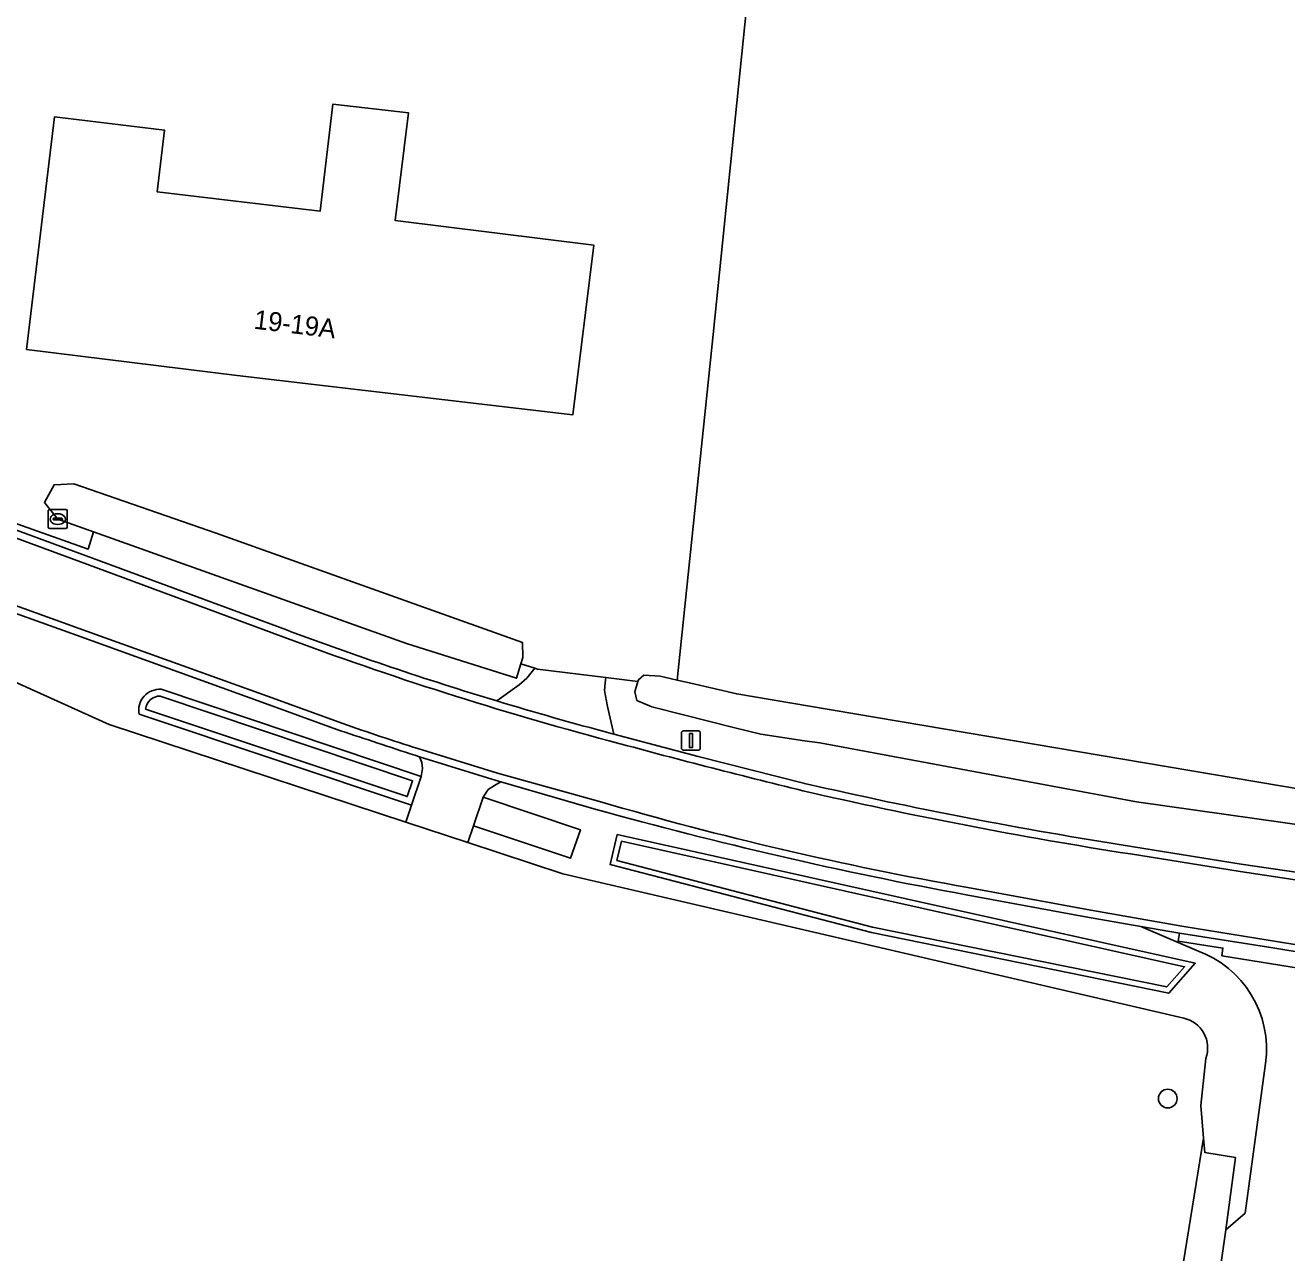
# Model space of a CAD drawing. Extents: x 162510 to 163918, y 388494 to 389774.
# Drawn here: x 162616.6 to 162682.9, y 389035.7 to 389100.2 of the extents above; entities that cross this region are included whole.
import ezdxf

# ---------------------------------------------------------------- set-up
doc = ezdxf.new("R2010")
doc.units = 0
for name, color, linetype in [('IMGEO_Berm_groen', 7, 'Continuous'), ('IMGEO_Boom', 7, 'Continuous'), ('IMGEO_Bouwland', 7, 'Continuous'), ('IMGEO_Erf', 7, 'Continuous'), ('IMGEO_Groenvoorziening', 7, 'Continuous'), ('IMGEO_Lichtmast', 7, 'Continuous'), ('IMGEO_Oever', 7, 'Continuous'), ('IMGEO_Pand', 7, 'Continuous'), ('IMGEO_Pand_nummerreeks', 7, 'Continuous'), ('IMGEO_Rijbaan_lokaal_gesloten', 7, 'Continuous'), ('IMGEO_Rijbaan_lokaal_halfverhard', 7, 'Continuous'), ('IMGEO_Rijbaan_lokaal_onverhard', 7, 'Continuous'), ('IMGEO_Rioolput', 7, 'Continuous'), ('IMGEO_Voetpad_open', 7, 'Continuous'), ('IMGEO_Waterloop', 7, 'Continuous')]:
    doc.layers.add(name, color=color, linetype=linetype)

msp = doc.modelspace()

# ---------------------------------------------------------------- linework, layer by layer
at = {"layer": 'IMGEO_Berm_groen'}
for points in [[(162599.769, 389075.181), (162599.005, 389075.013), (162598.439, 389074.769), (162598.136, 389073.919), (162597.772, 389072.896), (162605.424, 389070.178), (162605.91, 389071.318), (162613.301, 389068.852), (162612.506, 389067.31), (162621.016, 389063.464), (162636.603, 389058.338), (162636.901, 389059.229), (162622.591, 389064.006)], [(162633.167, 389063.141), (162629.224, 389064.578), (162619.309, 389068.164), (162606.622, 389072.695), (162599.769, 389075.181)], [(162623.752, 389065.315), (162637.408, 389060.743), (162637.478, 389061.162), (162637.435, 389061.466), (162637.328, 389061.772), (162637.079, 389061.849)]]:
    msp.add_lwpolyline(points, dxfattribs=at)
for centre, radius, start, end in [((162623.672, 389064.216), 1.102, 85.85497, 191.00304), ((163018.716, 390223.963), 1223.174, 251.626885, 251.819865)]:
    msp.add_arc(centre, radius, start, end, dxfattribs=at)
at = {"layer": 'IMGEO_Boom'}
msp.add_circle((162676.627, 389043.825), 0.489, dxfattribs=at)
at = {"layer": 'IMGEO_Bouwland'}
msp.add_lwpolyline([(162655.166, 389107.621), (162652.745, 389083.952), (162650.857, 389065.794), (162651.566, 389065.632), (162653.989, 389065.078), (162657.8, 389064.433), (162686.069, 389059.649), (162688.964, 389059.201), (162702.649, 389057.082), (162731.841, 389053.7), (162748.803, 389052.862), (162762.9, 389052.38), (162768.724, 389052.581), (162789.49, 389053.299), (162788.462, 389081.4), (162784.276, 389122.828)], dxfattribs=at)
at = {"layer": 'IMGEO_Erf'}
for points in [[(162610.637, 389075.969), (162619.919, 389072.683), (162620.188, 389073.585), (162618.326, 389074.249), (162617.612, 389075.122), (162618.128, 389076.056), (162619.16, 389076.114), (162626.637, 389073.516), (162642.734, 389067.769), (162642.75, 389066.991), (162642.646, 389066.648), (162643.381, 389066.421), (162643.518, 389066.379), (162647.102, 389065.938), (162648.643, 389065.749), (162648.795, 389065.73), (162648.82, 389065.815), (162649.111, 389066.053), (162649.957, 389066), (162650.857, 389065.794), (162652.745, 389083.952), (162655.166, 389107.621)], [(162677.463, 389048.046), (162644.844, 389055.627), (162639.858, 389057.267), (162636.603, 389058.338), (162621.016, 389063.464), (162612.506, 389067.31), (162605.424, 389070.178), (162597.772, 389072.896), (162592.401, 389074.784), (162572.538, 389080.978)], [(162663.551, 389030.577), (162675.729, 389028.773), (162674.379, 389019.647), (162674.908, 389019.57), (162678.508, 389041.745), (162678.361, 389043.464), (162678.629, 389045.931)]]:
    msp.add_lwpolyline(points, dxfattribs=at)
msp.add_lwpolyline([(162618.144, 389095.37), (162623.932, 389094.677), (162623.545, 389091.44), (162632.094, 389090.417), (162632.766, 389096.037), (162636.741, 389095.589), (162636.045, 389089.931), (162646.476, 389088.646), (162645.378, 389079.737), (162627.737, 389081.795), (162616.682, 389083.157)], close=True, dxfattribs=at)
msp.add_arc((162677.114, 389046.475), 1.609, 340.25405, 77.48187, dxfattribs=at)
at = {"layer": 'IMGEO_Groenvoorziening'}
for points in [[(162620.188, 389073.585), (162619.919, 389072.683), (162610.637, 389075.969), (162592.606, 389084.643), (162583.595, 389089.671), (162583.138, 389090.012), (162582.949, 389089.105), (162583.143, 389087.072), (162583.689, 389085.599), (162584.363, 389085.356), (162588.931, 389083.662), (162597.729, 389080.442), (162608.065, 389076.654), (162620.144, 389072.2), (162630.325, 389068.434)], [(162641.376, 389064.706), (162642.557, 389065.555), (162642.952, 389065.907), (162643.381, 389066.421), (162642.646, 389066.648), (162642.417, 389065.896), (162636.638, 389067.722), (162620.188, 389073.585)], [(162685.89, 389057.87), (162674.992, 389059.401), (162658.351, 389062.5), (162657.545, 389062.618), (162655.254, 389062.955), (162653.814, 389063.319), (162651.193, 389063.981), (162649.522, 389064.403), (162648.74, 389064.73), (162648.635, 389065.18), (162648.795, 389065.73), (162648.643, 389065.749), (162647.102, 389065.938), (162647.067, 389065.657), (162647.038, 389065.248), (162647.194, 389064.421), (162647.521, 389062.964), (162651.961, 389061.787), (162657.553, 389060.375)], [(162641.596, 389060.449), (162641.251, 389060.258), (162640.933, 389060.049), (162640.657, 389059.656), (162645.77, 389057.944), (162645.246, 389056.444), (162640.151, 389058.145), (162639.858, 389057.267), (162644.844, 389055.627), (162677.463, 389048.046)], [(162646.599, 389059.011), (162641.596, 389060.449)], [(162674.728, 389057.063), (162680.49, 389056.14), (162693.54, 389054.23), (162703.586, 389052.824), (162714.112, 389051.432), (162724.747, 389050.133), (162731.224, 389049.502)], [(162678.161, 389051.594), (162675.204, 389052.865), (162672.306, 389053.366), (162666.038, 389054.524)], [(162678.629, 389045.931), (162678.361, 389043.464), (162678.508, 389041.745), (162678.572, 389040.995), (162680.18, 389040.722), (162679.686, 389036.939), (162680.695, 389037.813), (162681.767, 389045.668)], [(162678.556, 389029.103), (162679.686, 389036.939), (162680.18, 389040.722), (162678.572, 389040.995), (162678.508, 389041.745), (162674.908, 389019.57)]]:
    msp.add_lwpolyline(points, dxfattribs=at)
msp.add_lwpolyline([(162647.704, 389057.694), (162678.074, 389050.928), (162676.679, 389049.359), (162661.055, 389052.542), (162647.33, 389056.11)], close=True, dxfattribs=at)
for centre, radius, start, end in [((162694.824, 389241.388), 184.589, 249.54808, 253.16879), ((162712.777, 389300.562), 246.454, 257.05152, 261.11879), ((162705.983, 389271.927), 221.042, 254.41588, 259.58886), ((162676.321, 389046.414), 5.497, 352.19997, 70.44146), ((162677.114, 389046.475), 1.609, 340.25405, 77.48187)]:
    msp.add_arc(centre, radius, start, end, dxfattribs=at)
at = {"layer": 'IMGEO_Lichtmast'}
for p, q in [((162651.182, 389063.127), (162651.972, 389063.127)), ((162651.972, 389063.127), (162651.182, 389063.127)), ((162651.082, 389062.227), (162651.082, 389063.027)), ((162651.082, 389063.027), (162651.082, 389062.227)), ((162652.072, 389063.027), (162652.072, 389062.227)), ((162652.072, 389062.227), (162652.072, 389063.027)), ((162651.972, 389062.127), (162651.182, 389062.127)), ((162651.182, 389062.127), (162651.972, 389062.127))]:
    msp.add_line(p, q, dxfattribs=at)
msp.add_lwpolyline([(162651.502, 389063.002), (162651.652, 389063.002), (162651.652, 389062.252), (162651.502, 389062.252), (162651.502, 389063.002)], dxfattribs=at)
for centre, start, end in [((162651.182, 389063.027), 90, 180), ((162651.182, 389063.027), 90, 180), ((162651.972, 389063.027), 0, 90), ((162651.972, 389063.027), 360, 90), ((162651.182, 389062.227), 180, 270), ((162651.182, 389062.227), 180, 270), ((162651.972, 389062.227), 270, 0), ((162651.972, 389062.227), 270, 0)]:
    msp.add_arc(centre, 0.1, start, end, dxfattribs=at)
at = {"layer": 'IMGEO_Oever'}
for points in [[(162622.591, 389064.006), (162636.901, 389059.229), (162637.408, 389060.743), (162623.752, 389065.315)], [(162623.696, 389064.957), (162636.955, 389060.518), (162636.675, 389059.682), (162622.934, 389064.269)]]:
    msp.add_lwpolyline(points, dxfattribs=at)
for points in [[(162647.704, 389057.694), (162647.33, 389056.11), (162661.055, 389052.542), (162676.679, 389049.359), (162678.074, 389050.928)], [(162647.928, 389057.337), (162677.511, 389050.746), (162676.57, 389049.688), (162661.123, 389052.834), (162647.69, 389056.327)]]:
    msp.add_lwpolyline(points, close=True, dxfattribs=at)
for centre, radius, start, end in [((162623.672, 389064.216), 1.102, 85.85497, 191.00304), ((162623.668, 389064.222), 0.735, 87.80627, 176.35068)]:
    msp.add_arc(centre, radius, start, end, dxfattribs=at)
at = {"layer": 'IMGEO_Pand'}
msp.add_lwpolyline([(162632.766, 389096.037), (162632.094, 389090.417), (162623.545, 389091.44), (162623.932, 389094.677), (162618.144, 389095.37), (162616.682, 389083.157), (162627.737, 389081.795), (162645.378, 389079.737), (162646.476, 389088.646), (162636.045, 389089.931), (162636.741, 389095.589)], close=True, dxfattribs=at)
at = {"layer": 'IMGEO_Rijbaan_lokaal_gesloten'}
for points in [[(162630.186, 389068.059), (162619.847, 389071.883), (162607.927, 389076.278), (162597.591, 389080.066), (162588.792, 389083.287), (162584.227, 389084.98)], [(162575.34, 389084.366), (162584.931, 389080.923), (162592.748, 389078.167), (162606.773, 389073.076), (162619.448, 389068.517), (162629.327, 389064.949), (162633.3, 389063.513)], [(162637.231, 389062.201), (162641.418, 389060.909), (162646.781, 389059.42)], [(162731.185, 389049.104), (162724.699, 389049.736), (162714.06, 389051.035), (162703.531, 389052.428), (162693.483, 389053.834), (162684.499, 389055.134), (162680.427, 389055.745), (162674.666, 389056.668)], [(162666.117, 389054.911), (162672.393, 389053.755), (162677.364, 389052.884), (162683.195, 389051.941), (162688.731, 389051.06), (162689.512, 389050.943), (162691.443, 389050.652), (162699.62, 389049.498), (162710.01, 389048.078)]]:
    msp.add_lwpolyline(points, dxfattribs=at)
for centre, radius, start, end in [((162694.778, 389241.263), 184.855, 249.54836, 255.11406), ((162695.7, 389243.931), 190.905, 250.92129, 252.16509), ((162765.105, 389498.178), 451.22, 254.86428, 256.19786), ((162712.585, 389299.535), 245.809, 257.0402, 261.12602), ((162697.827, 389234.609), 182.474, 253.75498, 259.99234)]:
    msp.add_arc(centre, radius, start, end, dxfattribs=at)
at = {"layer": 'IMGEO_Rijbaan_lokaal_halfverhard'}
for points in [[(162630.325, 389068.434), (162620.144, 389072.2), (162608.065, 389076.654), (162597.729, 389080.442), (162588.931, 389083.662), (162584.363, 389085.356), (162583.689, 389085.599)], [(162584.227, 389084.98), (162588.792, 389083.287), (162597.591, 389080.066), (162607.927, 389076.278), (162619.847, 389071.883), (162630.186, 389068.059)], [(162633.3, 389063.513), (162629.327, 389064.949), (162619.448, 389068.517), (162606.773, 389073.076), (162592.748, 389078.167), (162584.931, 389080.923), (162575.34, 389084.366)], [(162575.172, 389084.009), (162584.785, 389080.564), (162592.545, 389077.801), (162592.692, 389077.749), (162599.769, 389075.181), (162606.622, 389072.695), (162619.309, 389068.164), (162629.224, 389064.578), (162633.167, 389063.141)], [(162647.521, 389062.964), (162647.392, 389062.998)], [(162657.553, 389060.375), (162651.961, 389061.787), (162647.521, 389062.964)], [(162637.079, 389061.849), (162637.328, 389061.772), (162641.34, 389060.522), (162641.596, 389060.449), (162646.599, 389059.011)], [(162646.781, 389059.42), (162641.418, 389060.909), (162637.231, 389062.201)], [(162674.666, 389056.668), (162680.427, 389055.745), (162684.499, 389055.134), (162693.483, 389053.834), (162703.531, 389052.428), (162714.06, 389051.035), (162724.699, 389049.736), (162731.185, 389049.104)], [(162731.224, 389049.502), (162724.747, 389050.133), (162714.112, 389051.432), (162703.586, 389052.824), (162693.54, 389054.23), (162680.49, 389056.14), (162674.728, 389057.063)], [(162666.038, 389054.524), (162672.306, 389053.366), (162675.204, 389052.865), (162677.242, 389052.512), (162682.152, 389051.732), (162687.557, 389050.846), (162689.455, 389050.561), (162689.512, 389050.943), (162688.731, 389051.06), (162683.195, 389051.941), (162677.364, 389052.884), (162672.393, 389053.755), (162666.117, 389054.911)]]:
    msp.add_lwpolyline(points, dxfattribs=at)
msp.add_lwpolyline([(162677.242, 389052.512), (162677.171, 389052.087), (162679.523, 389051.729), (162679.462, 389051.327), (162685.553, 389050.347), (162689.22, 389049.734), (162690.404, 389049.536), (162690.474, 389049.983), (162689.397, 389050.172), (162689.455, 389050.561), (162687.557, 389050.846), (162682.152, 389051.732)], close=True, dxfattribs=at)
for centre, radius, start, end in [((162694.824, 389241.388), 184.589, 249.54808, 253.16879), ((162694.778, 389241.263), 184.855, 249.54836, 255.11406), ((162695.81, 389244.987), 188.32, 253.19886, 255.10164), ((163018.716, 390223.963), 1223.174, 251.626885, 251.819865), ((162695.7, 389243.931), 190.905, 250.92129, 252.16509), ((162765.105, 389498.178), 451.22, 254.86428, 256.19786), ((162712.585, 389299.535), 245.809, 257.0402, 261.12602), ((162712.777, 389300.562), 246.454, 257.05152, 261.11879), ((162697.827, 389234.609), 182.474, 253.75498, 259.99234), ((162705.983, 389271.927), 221.042, 254.41588, 259.58886)]:
    msp.add_arc(centre, radius, start, end, dxfattribs=at)
at = {"layer": 'IMGEO_Rijbaan_lokaal_onverhard'}
for points in [[(162689.22, 389049.734), (162685.553, 389050.347), (162679.462, 389051.327), (162679.523, 389051.729), (162677.171, 389052.087), (162677.242, 389052.512), (162675.204, 389052.865), (162678.161, 389051.594)], [(162681.767, 389045.668), (162680.695, 389037.813), (162679.686, 389036.939), (162678.556, 389029.103), (162679.407, 389028.933), (162675.625, 389002.844), (162675.31, 389000), (162674.776, 388995.176), (162674.447, 388987.068), (162674.465, 388979.037), (162674.722, 388967.62), (162675.363, 388952.72)]]:
    msp.add_lwpolyline(points, dxfattribs=at)
msp.add_arc((162676.321, 389046.414), 5.497, 352.19997, 70.44146, dxfattribs=at)
at = {"layer": 'IMGEO_Rioolput'}
for p, q in [((162617.818, 389073.829), (162617.818, 389074.681)), ((162617.893, 389074.755), (162618.745, 389074.755)), ((162618.306, 389074.535), (162618.331, 389074.535)), ((162618.819, 389074.681), (162618.819, 389073.829)), ((162618.745, 389073.755), (162617.893, 389073.755)), ((162618.077, 389074.249), (162618.077, 389074.261)), ((162618.515, 389074.212), (162618.117, 389074.212)), ((162618.12, 389074.298), (162618.518, 389074.298)), ((162618.329, 389073.975), (162618.304, 389073.975)), ((162618.561, 389074.261), (162618.561, 389074.249))]:
    msp.add_line(p, q, dxfattribs=at)
for points in [[(162617.818, 389073.829), (162617.818, 389074.681)], [(162617.893, 389074.755), (162618.745, 389074.755)], [(162618.819, 389074.681), (162618.819, 389073.829)], [(162618.745, 389073.755), (162617.893, 389073.755)]]:
    msp.add_lwpolyline(points, dxfattribs=at)
for centre, radius, start, end in [((162617.895, 389074.679), 0.0765, 91.55205, 178.44795), ((162617.895, 389074.679), 0.0765, 91.55205, 178.44795), ((162618.743, 389074.679), 0.0765, 1.55205, 88.44795), ((162618.743, 389074.679), 0.0765, 1.55205, 88.44795), ((162617.895, 389073.831), 0.0765, 181.55205, 268.44795), ((162617.895, 389073.831), 0.0765, 181.55205, 268.44795), ((162618.117, 389074.258), 0.0403, 85.87752, 175.75265), ((162618.114, 389074.248), 0.0366, 178.93798, 274.71019), ((162618.518, 389074.255), 0.043, 264.86636, 352.45326), ((162618.522, 389074.26), 0.0386, 1.73085, 96.63898), ((162618.743, 389073.831), 0.0765, 271.55205, 358.44795), ((162618.743, 389073.831), 0.0765, 271.55205, 358.44795)]:
    msp.add_arc(centre, radius, start, end, dxfattribs=at)
for centre, major_axis, ratio, start_param, end_param in [((162618.305, 389074.255), (-0.387, 0.002), 0.722429, 4.712389, 7.853982), ((162618.33, 389074.255), (-0.39, 0.002), 0.717154, 1.570796, 4.712389)]:
    msp.add_ellipse(centre, major_axis=major_axis, ratio=ratio, start_param=start_param, end_param=end_param, dxfattribs=at)
at = {"layer": 'IMGEO_Voetpad_open'}
for points in [[(162647.038, 389065.248), (162647.067, 389065.657), (162647.102, 389065.938), (162643.518, 389066.379), (162643.381, 389066.421), (162642.952, 389065.907), (162642.557, 389065.555), (162641.376, 389064.706)], [(162647.392, 389062.998), (162647.521, 389062.964), (162647.194, 389064.421), (162647.038, 389065.248)]]:
    msp.add_lwpolyline(points, dxfattribs=at)
msp.add_lwpolyline([(162640.933, 389060.049), (162641.251, 389060.258), (162641.596, 389060.449), (162641.34, 389060.522), (162637.328, 389061.772), (162637.435, 389061.466), (162637.478, 389061.162), (162637.408, 389060.743), (162636.901, 389059.229), (162636.603, 389058.338), (162639.858, 389057.267), (162640.151, 389058.145), (162640.657, 389059.656)], close=True, dxfattribs=at)
msp.add_arc((162695.81, 389244.987), 188.32, 253.19886, 255.10164, dxfattribs=at)
at = {"layer": 'IMGEO_Waterloop'}
for points in [[(162620.188, 389073.585), (162636.638, 389067.722), (162642.417, 389065.896), (162642.646, 389066.648), (162642.75, 389066.991), (162642.734, 389067.769), (162626.637, 389073.516), (162619.16, 389076.114), (162618.128, 389076.056), (162617.612, 389075.122), (162618.326, 389074.249)], [(162686.069, 389059.649), (162657.8, 389064.433), (162653.989, 389065.078), (162651.566, 389065.632), (162650.857, 389065.794), (162649.957, 389066), (162649.111, 389066.053), (162648.82, 389065.815), (162648.795, 389065.73), (162648.635, 389065.18), (162648.74, 389064.73), (162649.522, 389064.403), (162651.193, 389063.981), (162653.814, 389063.319), (162655.254, 389062.955), (162657.545, 389062.618), (162658.351, 389062.5), (162674.992, 389059.401), (162685.89, 389057.87), (162685.973, 389058.455)], [(162640.657, 389059.656), (162640.151, 389058.145), (162645.246, 389056.444), (162645.77, 389057.944)], [(162647.928, 389057.337), (162647.69, 389056.327), (162661.123, 389052.834), (162676.57, 389049.688), (162677.511, 389050.746)]]:
    msp.add_lwpolyline(points, close=True, dxfattribs=at)
msp.add_lwpolyline([(162622.934, 389064.269), (162636.675, 389059.682), (162636.955, 389060.518), (162623.696, 389064.957)], dxfattribs=at)
msp.add_arc((162623.668, 389064.222), 0.735, 87.80627, 176.35068, dxfattribs=at)

# ---------------------------------------------------------------- texts
at = {"layer": 'IMGEO_Pand_nummerreeks'}
msp.add_text('19-19A', height=1, rotation=353.14996, dxfattribs=at).set_placement((162628.582, 389084.257))

doc.saveas('drawing.dxf')
